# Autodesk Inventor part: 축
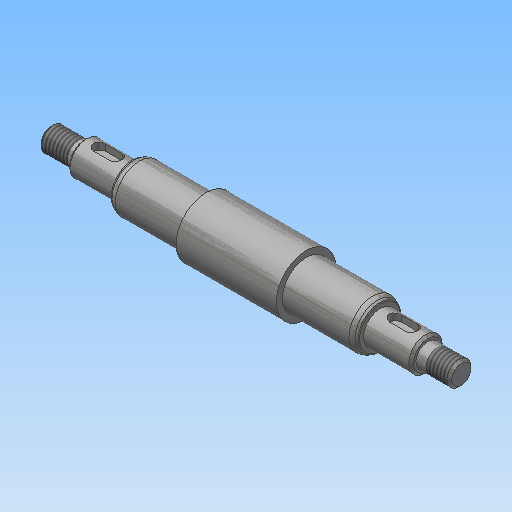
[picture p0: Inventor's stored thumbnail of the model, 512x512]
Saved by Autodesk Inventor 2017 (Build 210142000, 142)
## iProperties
Created: 2020-05
Part Number: 축
Material: 강철, 연강
Document SubType Name: Modeling
Designer: mduedu
Density: 1 g/cm^3
Appearance: 강철
Author: mduedu
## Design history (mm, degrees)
sketch "스케치1"
  geometry: L1 (0, 0)-(21, 0); L2 (21, 0)-(21, 12.5); L3 (21, 12.5)-(0, 12.5); L4 (0, 12.5)-(0, 0); L5 (21, 0)-(52, 0); L6 (52, 0)-(52, 10); L7 (52, 10)-(21, 10); L8 (21, 10)-(21, 0); L9 (52, 0)-(72, 0); L10 (72, 0)-(72, 7); L11 (72, 7)-(52, 7); L12 (52, 7)-(52, 0); L13 (72, 0)-(86, 0); L14 (86, 0)-(86, 5); L15 (86, 5)-(72, 5); L16 (72, 5)-(72, 0); L17 (0, 0)-(-21, 0); L18 (-21, 0)-(-21, 12.5); L19 (-21, 12.5)-(0, 12.5); L20 (-21, 0)-(-52, 0); L21 (-52, 0)-(-52, 10); L22 (-52, 10)-(-21, 10); L23 (-21, 10)-(-21, 0); L24 (-52, 0)-(-72, 0); L25 (-72, 0)-(-72, 7); L26 (-72, 7)-(-52, 7); L27 (-52, 7)-(-52, 0); L28 (-72, 0)-(-86, 0); L29 (-86, 0)-(-86, 5); L30 (-86, 5)-(-72, 5); L31 (-72, 5)-(-72, 0)
  constraints: 62 end point, 11 symmetric about line, 8 parallel, 4 horizontal, 4 perpendicular
  dimensions: "d0" = 172 distance between parallel lines of L14 L29; "d2" = 25 diameter of L3 L1; "d3" = 20 diameter of L7 L5; "d4" = 14 diameter of L11 L9; "d5" = 10 diameter of L15 L13; "d6" = 42 distance of L2.end L18.end; "d7" = 31 distance of L6.end L7.end; "d8" = 20 distance of L10.end L11.end; "d9" = 14 distance of L14.end L15.end (derived)
revolve "회전1" sketch "스케치1" stored, may be unused: angle "d10" = 90 deg
sketch "스케치2"
  geometry: L1 (72, -5)-(72, -7) reference; L2 (72, -7)-(52, -7) reference; L3 (52, -7)-(52, -10) reference; L4 (52, -10)-(21, -10) reference; L5 (21, -10)-(21, -12.5) reference; L6 (21, -12.5)-(-21, -12.5) reference; L7 (-21, -12.5)-(-21, -10) reference; L8 (-21, -10)-(-52, -10) reference; L9 (-52, -10)-(-52, -7) reference; L10 (-52, -7)-(-72, -7) reference; L11 (-72, -7)-(-72, -5) reference; L12 (-72, -5)-(-86, -5) reference; L13 (-86, -5)-(-86, 5) reference; L14 (-86, 5)-(-72, 5) reference; L15 (-72, 5)-(-72, 7) reference; L16 (-72, 7)-(-52, 7) reference; L17 (-52, 7)-(-52, 10) reference; L18 (-52, 10)-(-21, 10) reference; L19 (-21, 10)-(-21, 12.5) reference; L20 (-21, 12.5)-(21, 12.5) reference; L21 (21, 12.5)-(21, 10) reference; L22 (21, 10)-(52, 10) reference; L23 (52, 10)-(52, 7) reference; L24 (52, 7)-(72, 7) reference; L25 (72, 7)-(72, 5) reference; L26 (72, 5)-(86, 5) reference; L27 (86, 5)-(86, -5) reference; L28 (86, -5)-(72, -5) reference; L29 (-86, 0)-(86, 0); L30 (0, -12.5)-(0, 12.5); L31 (-52, 8.85)-(-50.008, 10); L32 (-50.008, 10)-(-52, 10); L33 (-52, 10)-(-52, 8.85); 1 further point
  constraints: 10 end point, 4 midpoint, 2 collinear, 2 point on line
  dimensions: "d11" = 17.7 diameter of L31.start L29; "d12" = 30 deg angle of L31 L32
revolve "회전2" sketch "스케치2" stored, may be unused: angle "d13" = 90 deg
fillet "모깎기1" dims "d14" = 4, "d15" = 0.5
node "작업 평면1"
sketch "스케치3"
  geometry: L1 (-6, 2.5)-(6, 2.5); L2 (6, 2.5)-(6, -2.5); L3 (6, -2.5)-(-6, -2.5); L4 (-6, -2.5)-(-6, 2.5); L5 (-10, 8.561)-(-10, -8.561) reference; 2 further points
  constraints: 8 end point, 2 parallel, 1 horizontal, 1 horizontal alignment, 1 midpoint, 1 perpendicular
  dimensions: "d16" = 5 distance of L1.end L2.end; "d18" = 4 distance between parallel lines of L4 L5; "d19" = 12 distance of L1.start L1.end
extrude "돌출1" cut sketch "스케치3" distance "d20" = 3; taper "d21" = 0 deg
fillet "모깎기2" dims "d22" = 2.5
fillet "모깎기3" dims "d23" = 2.5
feature "스레드1" dims "d24" = 12, "d25" = 0
feature "스레드2" dims "d26" = 10, "d27" = 0
chamfer "모따기1" distance "d28" = 1; stored, may be unused: second distance "d29" = 2, angle "d30" = 45 deg
chamfer "모따기2" distance "d31" = 1; stored, may be unused: second distance "d32" = 2, angle "d33" = 45 deg
node "솔리드1"
mirror "대칭1"
mirror "대칭2"
node "절단 모서리 투영1"
